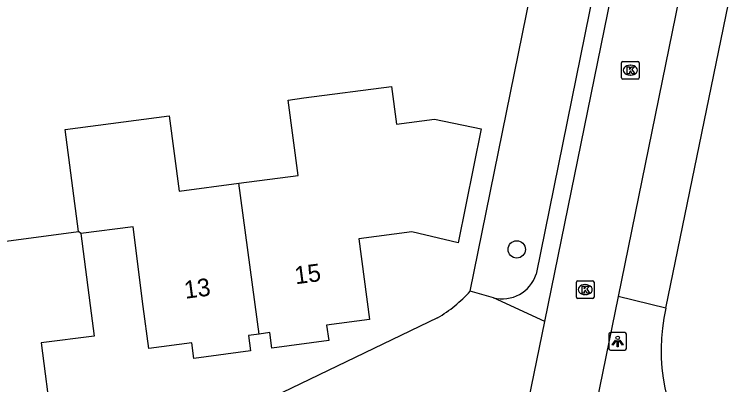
# Model space of a CAD drawing. Extents: x 163427 to 164190, y 380331 to 381641.
# Drawn here: x 163649.13 to 163689.76, y 381388.2 to 381409.13 of the extents above; entities that cross this region are included whole.
import ezdxf

# ---------------------------------------------------------------- set-up
doc = ezdxf.new("R2010")
doc.units = 0
for name, color, linetype in [('IMGEO_Boom', 7, 'Continuous'), ('IMGEO_Fietspad_open', 7, 'Continuous'), ('IMGEO_Groenvoorziening', 7, 'Continuous'), ('IMGEO_Kolk', 7, 'Continuous'), ('IMGEO_Lichtpunt', 7, 'Continuous'), ('IMGEO_Pand', 7, 'Continuous'), ('IMGEO_Pand_nummerreeks', 7, 'Continuous'), ('IMGEO_Voetpad_open', 7, 'Continuous')]:
    doc.layers.add(name, color=color, linetype=linetype)

msp = doc.modelspace()

# ---------------------------------------------------------------- linework, layer by layer
at = {"layer": 'IMGEO_Boom'}
msp.add_circle((163677.543, 381395.844), 0.489, dxfattribs=at)
at = {"layer": 'IMGEO_Fietspad_open'}
for points in [[(163679.125, 381391.772), (163685.892, 381424.838), (163689.574, 381424.058), (163683.28, 381393.186)], [(163683.28, 381393.186), (163681.363, 381383.781), (163677.639, 381384.509), (163679.125, 381391.772)]]:
    msp.add_lwpolyline(points, dxfattribs=at)
at = {"layer": 'IMGEO_Groenvoorziening'}
msp.add_lwpolyline([(163674.917, 381393.48), (163681.985, 381428.255)], dxfattribs=at)
at = {"layer": 'IMGEO_Kolk'}
for p, q in [((163683.472, 381405.552), (163683.472, 381406.404)), ((163683.547, 381406.478), (163684.399, 381406.478)), ((163683.96, 381406.258), (163683.985, 381406.258)), ((163684.473, 381406.404), (163684.473, 381405.552)), ((163684.399, 381405.478), (163683.547, 381405.478)), ((163683.983, 381405.698), (163683.958, 381405.698)), ((163680.917, 381393.147), (163680.917, 381393.999)), ((163680.992, 381394.073), (163681.844, 381394.073)), ((163681.918, 381393.999), (163681.918, 381393.147)), ((163681.405, 381393.853), (163681.43, 381393.853)), ((163681.428, 381393.293), (163681.403, 381393.293)), ((163681.844, 381393.073), (163680.992, 381393.073))]:
    msp.add_line(p, q, dxfattribs=at)
for points in [[(163683.472, 381405.552), (163683.472, 381406.404)], [(163683.547, 381406.478), (163684.399, 381406.478)], [(163683.793, 381406.178), (163683.916, 381406.178), (163683.916, 381406.027), (163684.046, 381406.178), (163684.21, 381406.178), (163684.064, 381406.027), (163684.217, 381405.778), (163684.065, 381405.778), (163683.98, 381405.942), (163683.916, 381405.875), (163683.916, 381405.778), (163683.793, 381405.778), (163683.793, 381406.178)], [(163684.473, 381406.404), (163684.473, 381405.552)], [(163684.399, 381405.478), (163683.547, 381405.478)], [(163680.917, 381393.147), (163680.917, 381393.999)], [(163680.992, 381394.073), (163681.844, 381394.073)], [(163681.918, 381393.999), (163681.918, 381393.147)], [(163681.238, 381393.773), (163681.361, 381393.773), (163681.361, 381393.622), (163681.491, 381393.773), (163681.655, 381393.773), (163681.509, 381393.622), (163681.662, 381393.373), (163681.51, 381393.373), (163681.425, 381393.537), (163681.361, 381393.47), (163681.361, 381393.373), (163681.238, 381393.373), (163681.238, 381393.773)], [(163681.844, 381393.073), (163680.992, 381393.073)]]:
    msp.add_lwpolyline(points, dxfattribs=at)
for centre, start, end in [((163683.549, 381406.402), 91.552, 178.448), ((163683.549, 381406.402), 91.552, 178.448), ((163684.397, 381406.402), 1.552, 88.448), ((163684.397, 381406.402), 1.552, 88.448), ((163683.549, 381405.554), 181.552, 268.448), ((163683.549, 381405.554), 181.552, 268.448), ((163684.397, 381405.554), 271.552, 358.448), ((163684.397, 381405.554), 271.552, 358.448), ((163680.994, 381393.997), 91.552, 178.448), ((163680.994, 381393.997), 91.552, 178.448), ((163681.842, 381393.997), 1.552, 88.448), ((163681.842, 381393.997), 1.552, 88.448), ((163680.994, 381393.149), 181.552, 268.448), ((163680.994, 381393.149), 181.552, 268.448), ((163681.842, 381393.149), 271.552, 358.448), ((163681.842, 381393.149), 271.552, 358.448)]:
    msp.add_arc(centre, 0.0765, start, end, dxfattribs=at)
for centre, major_axis, ratio, start_param, end_param in [((163683.959, 381405.978), (-0.387, 0.002), 0.722429, 4.712389, 7.853982), ((163683.984, 381405.978), (-0.39, 0.002), 0.717154, 1.570796, 4.712389), ((163681.404, 381393.573), (-0.387, 0.002), 0.722429, 4.712389, 7.853982), ((163681.429, 381393.573), (-0.39, 0.002), 0.717154, 1.570796, 4.712389)]:
    msp.add_ellipse(centre, major_axis=major_axis, ratio=ratio, start_param=start_param, end_param=end_param, dxfattribs=at)
at = {"layer": 'IMGEO_Lichtpunt'}
for p, q in [((163683.657, 381391.147), (163682.849, 381391.147)), ((163683.657, 381391.147), (163682.849, 381391.147)), ((163682.755, 381391.052), (163682.755, 381390.245)), ((163682.755, 381391.052), (163682.755, 381390.245)), ((163683.751, 381390.245), (163683.751, 381391.052)), ((163683.751, 381390.245), (163683.751, 381391.052)), ((163682.849, 381390.151), (163683.657, 381390.151)), ((163682.849, 381390.151), (163683.657, 381390.151))]:
    msp.add_line(p, q, dxfattribs=at)
for points in [[(163683.129, 381390.716), (163683.168, 381390.688), (163682.98, 381390.426), (163682.942, 381390.453), (163683.129, 381390.716)], [(163683.341, 381390.688), (163683.379, 381390.715), (163683.566, 381390.453), (163683.527, 381390.425), (163683.341, 381390.688)], [(163683.231, 381390.668), (163683.278, 381390.668), (163683.278, 381390.346), (163683.231, 381390.346), (163683.231, 381390.668)]]:
    msp.add_lwpolyline(points, dxfattribs=at)
msp.add_circle((163683.254, 381390.85), 0.0994, dxfattribs=at)
for centre, start, end in [((163682.849, 381391.052), 90, 180), ((163682.849, 381391.052), 90, 180), ((163683.657, 381391.052), 0, 90), ((163683.657, 381391.052), 0, 90), ((163682.849, 381390.245), 180, 270), ((163682.849, 381390.245), 180, 270), ((163683.657, 381390.245), 270, 0), ((163683.657, 381390.245), 270, 360)]:
    msp.add_arc(centre, 0.0946, start, end, dxfattribs=at)
at = {"layer": 'IMGEO_Pand'}
for points in [[(163661.817, 381399.592), (163665.179, 381400.034), (163664.619, 381404.291), (163665.503, 381404.408), (163670.46, 381405.06), (163670.736, 381402.925), (163672.89, 381403.204), (163675.534, 381402.666), (163674.226, 381396.227), (163671.617, 381396.841), (163668.613, 381396.44), (163669.22, 381391.88), (163666.793, 381391.561), (163666.908, 381390.69), (163663.689, 381390.267), (163663.574, 381391.139), (163662.97, 381391.059)], [(163652.765, 381396.859), (163652.006, 381402.631), (163657.886, 381403.405), (163658.447, 381399.148), (163661.817, 381399.592)], [(163662.97, 381391.059), (163661.817, 381399.592)], [(163644.152, 381391.394), (163647.514, 381391.837), (163646.954, 381396.094), (163652.765, 381396.859)], [(163652.894, 381396.738), (163652.765, 381396.859)], [(163662.97, 381391.059), (163662.366, 381390.98), (163662.48, 381390.108), (163659.271, 381389.687), (163659.157, 381390.559), (163656.73, 381390.24), (163656.422, 381392.62), (163655.84, 381397.119), (163652.894, 381396.738)], [(163652.894, 381396.738), (163653.477, 381392.239), (163653.644, 381390.947), (163650.648, 381390.559), (163651.232, 381386.05), (163651.54, 381383.67), (163649.109, 381383.35), (163649.225, 381382.469), (163646.011, 381382.047), (163645.896, 381382.92), (163645.29, 381382.84)]]:
    msp.add_lwpolyline(points, dxfattribs=at)
at = {"layer": 'IMGEO_Voetpad_open'}
for points in [[(163684.912, 381425.271), (163678.645, 381394.439)], [(163685.986, 381392.518), (163691.947, 381421.577)], [(163676.227, 381393.116), (163674.917, 381393.48)], [(163685.986, 381392.518), (163683.28, 381393.186)], [(163679.125, 381391.772), (163676.227, 381393.116)], [(163673.072, 381391.971), (163640.009, 381376.075)]]:
    msp.add_lwpolyline(points, dxfattribs=at)
for centre, radius, start, end in [((163676.738, 381395.054), 2.004, 255.2351, 342.1352), ((163668.615, 381399.303), 8.58, 301.2956, 317.263), ((163696.399, 381390.119), 10.686, 167.0234, 215.7266)]:
    msp.add_arc(centre, radius, start, end, dxfattribs=at)

# ---------------------------------------------------------------- texts
at = {"layer": 'IMGEO_Pand_nummerreeks'}
for s, p in [('15', (163665.041, 381393.872)), ('13', (163658.796, 381393.052))]:
    msp.add_text(s, height=1, rotation=7.4804, dxfattribs=at).set_placement(p)

doc.saveas('drawing.dxf')
